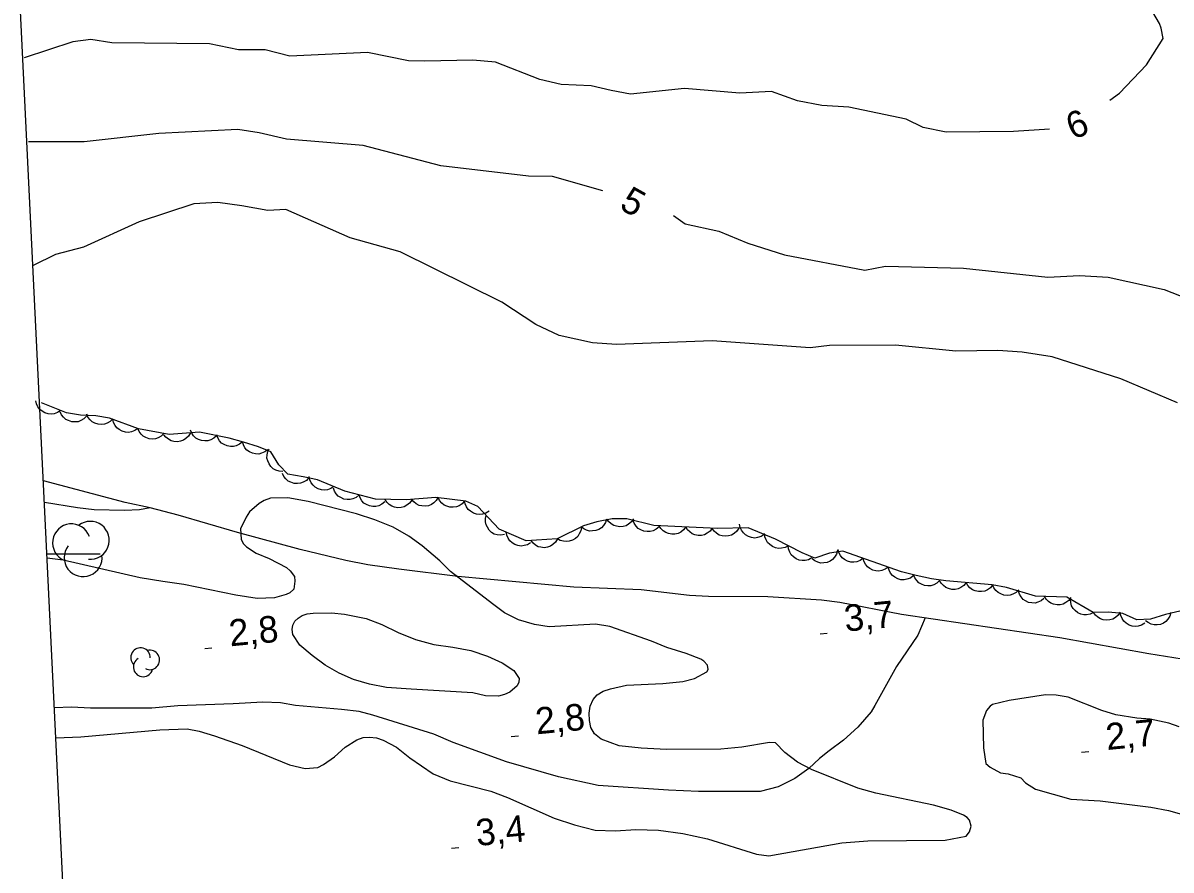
# Model space of a CAD drawing. Extents: x 336540 to 340074, y 5572036 to 5573747.
# Drawn here: x 336616 to 336745.5, y 5572364.3 to 5572459.9 of the extents above; entities that cross this region are included whole.
import ezdxf

# ---------------------------------------------------------------- set-up
doc = ezdxf.new("R2010")
doc.units = 0
for name, color, linetype in [('Niveau 1', 7, 'Continuous'), ('Niveau 2', 7, 'Continuous'), ('Niveau 22', 7, 'Continuous'), ('Niveau 3', 7, 'Continuous'), ('Niveau 44', 7, 'Continuous'), ('Niveau 60', 7, 'Continuous'), ('Niveau 61', 7, 'Continuous')]:
    doc.layers.add(name, color=color, linetype=linetype)

msp = doc.modelspace()

# ---------------------------------------------------------------- linework, layer by layer
at = {"layer": 'Niveau 1'}
for points in [[(336681.44, 5572440.96), (336675.75, 5572442.56), (336673.04, 5572442.6), (336663.17, 5572443.78), (336654.41, 5572446.05), (336645.76, 5572446.79), (336642.67, 5572447.49), (336640.29, 5572447.87), (336631.35, 5572447.41), (336622.95, 5572446.49), (336616.66, 5572446.48)], [(336689.41, 5572438.18), (336690.74, 5572437.24), (336694.51, 5572436.41), (336697.79, 5572435.05), (336701.93, 5572433.74), (336710.98, 5572432), (336713.32, 5572432.45), (336722.13, 5572432.24), (336731.65, 5572431.2), (336735.21, 5572431.39), (336738.42, 5572431.21), (336744.75, 5572429.83), (336750.81, 5572427.43)]]:
    msp.add_lwpolyline(points, dxfattribs=at)
at = {"layer": 'Niveau 2'}
for points in [[(336738.64, 5572451.17), (336739.72, 5572451.96), (336742.77, 5572455.17), (336744.66, 5572458.15), (336744.42, 5572459.32), (336744.22, 5572459.82), (336741.06, 5572465.25)], [(336731.81, 5572447.89), (336727.77, 5572447.63), (336720.16, 5572447.56), (336717.58, 5572448.11), (336715.67, 5572449.03), (336709.18, 5572450.39), (336706.14, 5572450.57), (336703.4, 5572451.12), (336700.45, 5572452.15), (336696.91, 5572451.97), (336690.64, 5572452.5), (336684.57, 5572451.84), (336682.37, 5572452.26), (336680.13, 5572452.8), (336676.74, 5572452.96), (336674.35, 5572453.53), (336669.33, 5572455.48), (336666.79, 5572455.7), (336661.38, 5572455.57), (336659.52, 5572455.63), (336654.9, 5572456.57), (336646.12, 5572456.13), (336643.37, 5572456.85), (336640.33, 5572456.86), (336637.08, 5572457.53), (336626.07, 5572457.65), (336623.68, 5572458.04), (336621.67, 5572457.77), (336616.17, 5572455.96)], [(336746.25, 5572417.02), (336739.86, 5572419.75), (336732.11, 5572422.23), (336728.72, 5572422.74), (336726, 5572422.94), (336721.25, 5572422.86), (336714.46, 5572423.53), (336707.02, 5572423.49), (336704.83, 5572423.22), (336693.79, 5572424.01), (336682.98, 5572423.6), (336680.26, 5572423.8), (336676.51, 5572424.64), (336673.9, 5572425.86), (336670.04, 5572428.38), (336658.58, 5572434.05), (336652.94, 5572435.63), (336645.67, 5572438.83), (336643.64, 5572438.72), (336640.73, 5572439.26), (336638.02, 5572439.62), (336635.31, 5572439.48), (336629.16, 5572437.45), (336622.87, 5572434.6), (336619.71, 5572433.75), (336617.19, 5572432.51)], [(336619.76, 5572379.24), (336622.56, 5572379.34), (336631.47, 5572380.14), (336634.56, 5572380.25), (336635.9, 5572379.98), (336637.65, 5572379.46), (336640.77, 5572378.35), (336646.1, 5572376.16), (336647.85, 5572375.75), (336649.3, 5572375.89), (336649.93, 5572376.2), (336651.17, 5572377.08), (336652.38, 5572378.17), (336653.7, 5572379.01), (336654.4, 5572379.25), (336655.14, 5572379.3), (336655.9, 5572379.22), (336656.65, 5572378.97), (336658.16, 5572378.16), (336659.66, 5572376.97), (336662.29, 5572375.16), (336664.23, 5572374.37), (336668.79, 5572373.21), (336670.68, 5572372.48), (336675.95, 5572370.16), (336678.24, 5572369.39), (336680.59, 5572368.79), (336682.86, 5572368.71), (336685.18, 5572368.87), (336687.71, 5572368.8), (336690.46, 5572368.44), (336693.23, 5572367.83), (336698.77, 5572366.11), (336700.16, 5572365.9), (336708.38, 5572367.37), (336711.34, 5572367.59), (336720.04, 5572367.69), (336722.41, 5572368.13), (336722.81, 5572368.6), (336722.98, 5572369.25), (336722.81, 5572369.92), (336722.54, 5572370.22), (336722.11, 5572370.5), (336720.72, 5572371.05), (336718.73, 5572371.61), (336712.22, 5572372.97), (336710.2, 5572373.56), (336704.98, 5572375.63), (336703.4, 5572376.46), (336701.96, 5572377.55), (336700.9, 5572378.66), (336700.25, 5572378.71), (336697.12, 5572378.15), (336694.76, 5572377.93), (336688.63, 5572377.92), (336685.75, 5572378.04), (336683.3, 5572378.32), (336681.26, 5572379.09), (336680.51, 5572379.69), (336680.1, 5572380.4), (336679.92, 5572381.18), (336679.9, 5572381.99), (336680.03, 5572382.79), (336680.35, 5572383.53), (336680.82, 5572384.08), (336681.49, 5572384.49), (336682.31, 5572384.77), (336684.11, 5572385.18), (336688.2, 5572385.35), (336690.45, 5572385.57), (336691.78, 5572385.91), (336693.16, 5572386.67), (336693.34, 5572386.94), (336693.25, 5572387.44), (336692.84, 5572387.89), (336692.49, 5572388.11), (336690.83, 5572388.73), (336688.65, 5572389.4), (336686.93, 5572390.14), (336682.22, 5572391.79), (336680.61, 5572392.06), (336675.39, 5572391.74), (336673.74, 5572392.02), (336671.94, 5572392.53), (336670.34, 5572393.34), (336669, 5572394.34), (336664.26, 5572397.99), (336663.04, 5572399.18), (336661.08, 5572400.9), (336659.57, 5572401.98), (336657.8, 5572402.99), (336655.72, 5572403.82), (336653.67, 5572404.51), (336648.19, 5572405.89), (336645.91, 5572406.31), (336643.94, 5572406.27), (336643.24, 5572406.01), (336642.66, 5572405.66), (336641.59, 5572404.72), (336641.2, 5572404.12), (336640.57, 5572402.79)], [(336640.57, 5572402.79), (336640.64, 5572401.65), (336640.87, 5572401.16), (336641.26, 5572400.76), (336642.33, 5572400.05), (336643.79, 5572399.45), (336645.76, 5572398.46), (336646.19, 5572398.07), (336646.66, 5572397.42), (336646.7, 5572396.89), (336646.59, 5572396), (336646.14, 5572395.58), (336645.72, 5572395.38), (336644.4, 5572395.01), (336642.47, 5572394.96), (336640.04, 5572395.31), (336634.18, 5572396.54), (336631.81, 5572396.85), (336629.27, 5572397.29), (336620.56, 5572399.28), (336618.77, 5572399.51)], [(336659.83, 5572384.73), (336657.04, 5572384.9), (336655.14, 5572385.26), (336653.33, 5572385.79), (336651.69, 5572386.53), (336650.14, 5572387.44), (336648.66, 5572388.51), (336647.26, 5572389.68), (336646.46, 5572390.89), (336646.4, 5572391.44), (336646.46, 5572391.95), (336646.7, 5572392.39), (336647.07, 5572392.73), (336647.54, 5572393.01), (336648.11, 5572393.21), (336648.76, 5572393.29), (336650.85, 5572393.33), (336652.32, 5572393.17), (336654.76, 5572392.69), (336656.53, 5572392.03), (336658.34, 5572391.12), (336660.3, 5572390.32), (336662.38, 5572389.77), (336664.51, 5572389.47), (336666.55, 5572389.06), (336668.44, 5572388.45), (336670.09, 5572387.69), (336671.41, 5572386.83), (336672, 5572385.93), (336671.96, 5572385.49), (336671.76, 5572385.1), (336670.96, 5572384.38), (336670.36, 5572384.1), (336669.67, 5572383.94), (336668.19, 5572383.97), (336666.77, 5572384.31), (336659.83, 5572384.73)], [(336746.46, 5572380.48), (336745.27, 5572380.89), (336743.19, 5572381.34), (336741.66, 5572381.45), (336739.32, 5572381.81), (336737.73, 5572382.3), (336733.91, 5572383.82), (336732.59, 5572384.05), (336731.38, 5572384.06), (336727.29, 5572383.42), (336725.39, 5572382.98), (336725.13, 5572382.81), (336724.72, 5572382.29), (336724.3, 5572381.21), (336724.38, 5572378.1), (336724.65, 5572376.33), (336725.12, 5572375.91), (336726.28, 5572375.29), (336727.16, 5572375.15), (336728.58, 5572374.71), (336729.13, 5572374.16), (336730.24, 5572373.42), (336734.22, 5572372.31)], [(336734.22, 5572372.31), (336737.53, 5572372.11), (336743.26, 5572371.39), (336745.26, 5572371.01), (336749.51, 5572369.81)]]:
    msp.add_lwpolyline(points, dxfattribs=at)
at = {"layer": 'Niveau 22'}
for points in [[(336746.78, 5572388.11), (336743.04, 5572388.69), (336733, 5572390.49), (336715.14, 5572393.15), (336708.18, 5572394.48), (336706.11, 5572394.76), (336700.06, 5572395.12), (336693.35, 5572395.17), (336691.23, 5572395.28), (336685.77, 5572395.92), (336678.18, 5572396.21), (336665.09, 5572397.41), (336658.42, 5572398.24), (336654.93, 5572398.74), (336652.44, 5572399.22), (336647.3, 5572400.46), (336640.25, 5572402.38), (336633.54, 5572404.36), (336630.38, 5572405.18), (336627.58, 5572405.79), (336618.34, 5572408.23)], [(336630.38, 5572405.18), (336629.18, 5572404.95), (336627.47, 5572404.89), (336624.06, 5572404.94), (336622.18, 5572405.17), (336618.46, 5572405.79)], [(336717.79, 5572392.75), (336716.98, 5572390.81), (336714.58, 5572387.29), (336712.13, 5572382.86), (336711.69, 5572382.17), (336710.2, 5572380.42), (336708.6, 5572378.95), (336706.98, 5572377.76), (336705.87, 5572376.88), (336704.68, 5572375.78), (336703.1, 5572374.62), (336701.21, 5572373.69), (336699.19, 5572373.16), (336692.24, 5572373.16), (336688.85, 5572373.31), (336680.93, 5572373.84), (336676.44, 5572374.81), (336670.58, 5572376.53), (336664.55, 5572378.7), (336662.38, 5572379.62), (336655.49, 5572381.77), (336653.96, 5572382.19), (336651.98, 5572382.43), (336646.77, 5572382.87), (336645.07, 5572383.17), (336643.09, 5572383.24), (336639.76, 5572383.04), (336633.49, 5572382.84), (336630.56, 5572382.57), (336623.66, 5572382.57), (336621.51, 5572382.69), (336619.58, 5572382.62)]]:
    msp.add_lwpolyline(points, dxfattribs=at)
at = {"layer": 'Niveau 3'}
for p, q in [((336705.94, 5572390.96), (336706.74, 5572391.04)), ((336636.54, 5572389.3), (336637.34, 5572389.38)), ((336671.11, 5572379.37), (336671.91, 5572379.45)), ((336735.44, 5572377.6), (336736.24, 5572377.68)), ((336664.39, 5572366.77), (336665.19, 5572366.85))]:
    msp.add_line(p, q, dxfattribs=at)
at = {"layer": 'Niveau 44'}
for points in [[(336620.28, 5572416.16), (336619.94, 5572415.93), (336619.55, 5572415.8), (336619.23, 5572415.74), (336618.88, 5572415.78), (336618.52, 5572415.89), (336618.19, 5572416.08), (336617.93, 5572416.28), (336617.73, 5572416.57), (336617.57, 5572416.9), (336617.49, 5572417.25)], [(336748.3, 5572393.92), (336744.89, 5572393.15), (336743.22, 5572392.62), (336741.68, 5572392.54), (336740.09, 5572393.24), (336738.42, 5572393.39), (336736.75, 5572393.38), (336733.76, 5572395.08), (336730.25, 5572395.22), (336726.98, 5572396.18), (336725.36, 5572396.49), (336720.13, 5572396.93), (336718.5, 5572397.17), (336716.79, 5572397.55), (336715.11, 5572397.97), (336708.51, 5572400.29), (336707.01, 5572400.06), (336705.36, 5572399.51), (336703.94, 5572400.08), (336700.92, 5572401.63), (336697.84, 5572402.92), (336694.33, 5572402.85), (336687.19, 5572403.19), (336684.16, 5572403.94), (336682.48, 5572403.92), (336680.76, 5572403.58), (336679.26, 5572403.13), (336676.28, 5572401.66), (336672.79, 5572401.46), (336669.74, 5572402.78), (336667.34, 5572405.34), (336665.97, 5572405.93), (336662.61, 5572406.36), (336659.27, 5572406.07), (336655.8, 5572406.14), (336652.33, 5572407.07), (336649.26, 5572408.32), (336647.63, 5572408.69), (336645.91, 5572408.96), (336644.91, 5572410.02), (336644, 5572411.5), (336642.59, 5572412.07), (336640.91, 5572412.59), (336639.29, 5572413.03), (336635.96, 5572413.72), (336632.54, 5572413.47), (336629.08, 5572414.1), (336625.81, 5572415.28), (336624.27, 5572415.55), (336622.52, 5572415.64), (336620.96, 5572415.9), (336618.11, 5572417.01)], [(336623.2, 5572415.53), (336622.92, 5572415.22), (336622.56, 5572415.02), (336622.26, 5572414.9), (336621.91, 5572414.87), (336621.54, 5572414.9), (336621.17, 5572415.02), (336620.88, 5572415.16), (336620.62, 5572415.4), (336620.39, 5572415.69), (336620.24, 5572416.02)], [(336626.18, 5572415.21), (336625.89, 5572414.91), (336625.54, 5572414.72), (336625.23, 5572414.6), (336624.88, 5572414.57), (336624.51, 5572414.6), (336624.15, 5572414.73), (336623.85, 5572414.87), (336623.6, 5572415.11), (336623.37, 5572415.4), (336623.23, 5572415.73)], [(336628.99, 5572414.13), (336628.65, 5572413.89), (336628.26, 5572413.75), (336627.94, 5572413.69), (336627.59, 5572413.72), (336627.23, 5572413.81), (336626.9, 5572414), (336626.63, 5572414.19), (336626.42, 5572414.47), (336626.25, 5572414.8), (336626.16, 5572415.15)], [(336631.93, 5572413.58), (336631.64, 5572413.28), (336631.28, 5572413.09), (336630.98, 5572412.97), (336630.63, 5572412.94), (336630.26, 5572412.97), (336629.9, 5572413.11), (336629.6, 5572413.25), (336629.35, 5572413.49), (336629.13, 5572413.79), (336628.98, 5572414.12)], [(336634.92, 5572413.64), (336634.71, 5572413.28), (336634.41, 5572413), (336634.14, 5572412.81), (336633.81, 5572412.7), (336633.45, 5572412.64), (336633.07, 5572412.67), (336632.75, 5572412.74), (336632.44, 5572412.91), (336632.15, 5572413.14), (336631.93, 5572413.43)], [(336637.87, 5572413.32), (336637.57, 5572413.03), (336637.21, 5572412.85), (336636.9, 5572412.73), (336636.55, 5572412.72), (336636.18, 5572412.76), (336635.83, 5572412.9), (336635.54, 5572413.05), (336635.29, 5572413.3), (336635.07, 5572413.6), (336634.94, 5572413.93)], [(336640.79, 5572412.62), (336640.47, 5572412.35), (336640.1, 5572412.19), (336639.78, 5572412.09), (336639.43, 5572412.1), (336639.07, 5572412.16), (336638.72, 5572412.32), (336638.44, 5572412.49), (336638.21, 5572412.75), (336638.01, 5572413.07), (336637.89, 5572413.41)], [(336643.66, 5572411.74), (336643.33, 5572411.48), (336642.95, 5572411.33), (336642.63, 5572411.25), (336642.28, 5572411.26), (336641.92, 5572411.34), (336641.58, 5572411.51), (336641.3, 5572411.69), (336641.08, 5572411.96), (336640.9, 5572412.28), (336640.79, 5572412.63)], [(336645.36, 5572409.29), (336644.94, 5572409.31), (336644.56, 5572409.44), (336644.26, 5572409.59), (336644.01, 5572409.83), (336643.79, 5572410.13), (336643.65, 5572410.49), (336643.56, 5572410.8), (336643.57, 5572411.15), (336643.64, 5572411.52), (336643.79, 5572411.84)], [(336648.28, 5572408.59), (336648, 5572408.28), (336647.65, 5572408.08), (336647.34, 5572407.95), (336646.99, 5572407.92), (336646.62, 5572407.94), (336646.26, 5572408.06), (336645.96, 5572408.2), (336645.7, 5572408.44), (336645.47, 5572408.73), (336645.32, 5572409.05)], [(336651.1, 5572407.57), (336650.75, 5572407.34), (336650.37, 5572407.22), (336650.04, 5572407.17), (336649.69, 5572407.21), (336649.34, 5572407.32), (336649.01, 5572407.52), (336648.75, 5572407.72), (336648.55, 5572408.01), (336648.4, 5572408.35), (336648.32, 5572408.7)], [(336653.95, 5572406.64), (336653.63, 5572406.36), (336653.26, 5572406.2), (336652.94, 5572406.1), (336652.59, 5572406.11), (336652.23, 5572406.17), (336651.88, 5572406.33), (336651.6, 5572406.5), (336651.36, 5572406.76), (336651.17, 5572407.07), (336651.05, 5572407.41)], [(336656.84, 5572405.86), (336656.53, 5572405.59), (336656.16, 5572405.42), (336655.84, 5572405.33), (336655.49, 5572405.33), (336655.13, 5572405.39), (336654.78, 5572405.55), (336654.5, 5572405.72), (336654.26, 5572405.98), (336654.06, 5572406.3), (336653.95, 5572406.64)], [(336659.88, 5572406.06), (336659.64, 5572405.72), (336659.32, 5572405.47), (336659.03, 5572405.3), (336658.69, 5572405.22), (336658.32, 5572405.19), (336657.95, 5572405.26), (336657.63, 5572405.36), (336657.34, 5572405.56), (336657.08, 5572405.82), (336656.88, 5572406.12)], [(336662.87, 5572406.38), (336662.66, 5572406.02), (336662.37, 5572405.74), (336662.11, 5572405.54), (336661.77, 5572405.42), (336661.41, 5572405.36), (336661.03, 5572405.39), (336660.71, 5572405.45), (336660.4, 5572405.62), (336660.11, 5572405.84), (336659.88, 5572406.12)], [(336665.84, 5572405.95), (336665.57, 5572405.63), (336665.22, 5572405.42), (336664.92, 5572405.28), (336664.57, 5572405.24), (336664.2, 5572405.25), (336663.83, 5572405.36), (336663.53, 5572405.49), (336663.27, 5572405.72), (336663.03, 5572406.01), (336662.87, 5572406.33)], [(336668.61, 5572404.79), (336668.25, 5572404.57), (336667.86, 5572404.46), (336667.54, 5572404.41), (336667.19, 5572404.46), (336666.84, 5572404.58), (336666.52, 5572404.79), (336666.26, 5572404.99), (336666.07, 5572405.29), (336665.92, 5572405.63), (336665.85, 5572405.98)], [(336670.34, 5572402.15), (336669.92, 5572402.08), (336669.52, 5572402.13), (336669.2, 5572402.22), (336668.9, 5572402.41), (336668.63, 5572402.66), (336668.42, 5572402.98), (336668.27, 5572403.26), (336668.21, 5572403.61), (336668.2, 5572403.98), (336668.28, 5572404.33)], [(336684.89, 5572403.95), (336684.66, 5572403.6), (336684.35, 5572403.34), (336684.07, 5572403.16), (336683.73, 5572403.07), (336683.36, 5572403.03), (336682.98, 5572403.09), (336682.67, 5572403.18), (336682.37, 5572403.37), (336682.09, 5572403.62), (336681.89, 5572403.91)], [(336679.02, 5572403.01), (336678.96, 5572402.6), (336678.79, 5572402.23), (336678.61, 5572401.95), (336678.35, 5572401.72), (336678.03, 5572401.52), (336677.66, 5572401.42), (336677.34, 5572401.36), (336676.99, 5572401.4), (336676.64, 5572401.5), (336676.33, 5572401.68)], [(336681.87, 5572403.91), (336681.75, 5572403.52), (336681.52, 5572403.18), (336681.3, 5572402.93), (336681, 5572402.75), (336680.66, 5572402.61), (336680.27, 5572402.57), (336679.95, 5572402.56), (336679.61, 5572402.66), (336679.28, 5572402.82), (336679, 5572403.05)], [(336687.78, 5572403.04), (336687.47, 5572402.76), (336687.1, 5572402.59), (336686.79, 5572402.49), (336686.43, 5572402.49), (336686.07, 5572402.54), (336685.72, 5572402.7), (336685.43, 5572402.86), (336685.2, 5572403.12), (336684.99, 5572403.43), (336684.87, 5572403.76)], [(336690.79, 5572403.02), (336690.54, 5572402.68), (336690.22, 5572402.44), (336689.93, 5572402.28), (336689.58, 5572402.21), (336689.21, 5572402.2), (336688.84, 5572402.28), (336688.53, 5572402.38), (336688.24, 5572402.59), (336687.98, 5572402.85), (336687.8, 5572403.16)], [(336693.79, 5572402.88), (336693.54, 5572402.54), (336693.21, 5572402.3), (336692.92, 5572402.14), (336692.58, 5572402.07), (336692.21, 5572402.05), (336691.83, 5572402.14), (336691.52, 5572402.24), (336691.24, 5572402.45), (336690.98, 5572402.71), (336690.79, 5572403.02)], [(336696.79, 5572402.9), (336696.56, 5572402.55), (336696.25, 5572402.29), (336695.97, 5572402.11), (336695.63, 5572402.01), (336695.27, 5572401.97), (336694.89, 5572402.03), (336694.57, 5572402.11), (336694.27, 5572402.3), (336694, 5572402.55), (336693.79, 5572402.84)], [(336699.64, 5572402.17), (336699.29, 5572401.94), (336698.9, 5572401.82), (336698.57, 5572401.77), (336698.22, 5572401.82), (336697.87, 5572401.94), (336697.55, 5572402.14), (336697.29, 5572402.34), (336697.09, 5572402.64), (336696.94, 5572402.97), (336696.87, 5572403.33)], [(336673.29, 5572401.24), (336672.94, 5572401.02), (336672.55, 5572400.91), (336672.22, 5572400.86), (336671.87, 5572400.92), (336671.52, 5572401.03), (336671.2, 5572401.24), (336670.95, 5572401.45), (336670.76, 5572401.74), (336670.61, 5572402.08), (336670.54, 5572402.43)], [(336676.33, 5572401.66), (336676.12, 5572401.3), (336675.82, 5572401.03), (336675.54, 5572400.84), (336675.21, 5572400.73), (336674.84, 5572400.68), (336674.46, 5572400.72), (336674.15, 5572400.79), (336673.84, 5572400.97), (336673.55, 5572401.21), (336673.34, 5572401.49)], [(336702.35, 5572400.9), (336701.99, 5572400.69), (336701.59, 5572400.61), (336701.26, 5572400.59), (336700.91, 5572400.66), (336700.57, 5572400.8), (336700.27, 5572401.03), (336700.03, 5572401.25), (336699.85, 5572401.56), (336699.73, 5572401.91), (336699.68, 5572402.27)], [(336705.02, 5572399.53), (336704.65, 5572399.32), (336704.26, 5572399.24), (336703.93, 5572399.22), (336703.58, 5572399.29), (336703.24, 5572399.43), (336702.93, 5572399.66), (336702.7, 5572399.88), (336702.52, 5572400.19), (336702.4, 5572400.54), (336702.35, 5572400.9)], [(336707.91, 5572400.36), (336707.79, 5572399.96), (336707.58, 5572399.61), (336707.36, 5572399.36), (336707.07, 5572399.17), (336706.73, 5572399.02), (336706.35, 5572398.96), (336706.02, 5572398.95), (336705.68, 5572399.04), (336705.35, 5572399.19), (336705.06, 5572399.41)], [(336710.8, 5572399.48), (336710.46, 5572399.24), (336710.08, 5572399.1), (336709.76, 5572399.03), (336709.41, 5572399.06), (336709.05, 5572399.15), (336708.71, 5572399.34), (336708.45, 5572399.52), (336708.23, 5572399.8), (336708.06, 5572400.13), (336707.97, 5572400.48)], [(336713.63, 5572398.49), (336713.3, 5572398.24), (336712.91, 5572398.1), (336712.59, 5572398.04), (336712.24, 5572398.06), (336711.88, 5572398.16), (336711.55, 5572398.34), (336711.28, 5572398.53), (336711.07, 5572398.81), (336710.89, 5572399.14), (336710.8, 5572399.48)], [(336716.46, 5572397.5), (336716.13, 5572397.25), (336715.74, 5572397.11), (336715.42, 5572397.04), (336715.07, 5572397.07), (336714.71, 5572397.16), (336714.38, 5572397.35), (336714.11, 5572397.53), (336713.9, 5572397.81), (336713.72, 5572398.14), (336713.63, 5572398.49)], [(336719.43, 5572396.96), (336719.12, 5572396.68), (336718.76, 5572396.5), (336718.45, 5572396.39), (336718.09, 5572396.38), (336717.73, 5572396.42), (336717.37, 5572396.57), (336717.09, 5572396.72), (336716.84, 5572396.98), (336716.63, 5572397.28), (336716.5, 5572397.62)], [(336722.42, 5572396.74), (336722.16, 5572396.41), (336721.82, 5572396.18), (336721.53, 5572396.04), (336721.18, 5572395.97), (336720.81, 5572395.97), (336720.44, 5572396.07), (336720.14, 5572396.18), (336719.86, 5572396.4), (336719.61, 5572396.67), (336719.43, 5572396.99)], [(336725.41, 5572396.49), (336725.15, 5572396.16), (336724.81, 5572395.93), (336724.52, 5572395.78), (336724.17, 5572395.72), (336723.8, 5572395.72), (336723.43, 5572395.82), (336723.13, 5572395.93), (336722.85, 5572396.15), (336722.6, 5572396.42), (336722.42, 5572396.74)], [(336728.36, 5572395.92), (336728.06, 5572395.62), (336727.7, 5572395.43), (336727.4, 5572395.31), (336727.04, 5572395.29), (336726.68, 5572395.33), (336726.32, 5572395.46), (336726.03, 5572395.61), (336725.77, 5572395.85), (336725.55, 5572396.15), (336725.41, 5572396.48)], [(336731.2, 5572394.94), (336730.88, 5572394.67), (336730.51, 5572394.52), (336730.19, 5572394.43), (336729.84, 5572394.44), (336729.47, 5572394.51), (336729.13, 5572394.68), (336728.85, 5572394.85), (336728.63, 5572395.12), (336728.44, 5572395.44), (336728.33, 5572395.78)], [(336734.24, 5572395.06), (336733.99, 5572394.72), (336733.67, 5572394.48), (336733.38, 5572394.32), (336733.04, 5572394.24), (336732.67, 5572394.23), (336732.29, 5572394.31), (336731.98, 5572394.41), (336731.7, 5572394.61), (336731.43, 5572394.87), (336731.24, 5572395.18)], [(336736.79, 5572393.36), (336736.41, 5572393.17), (336736.01, 5572393.11), (336735.68, 5572393.1), (336735.34, 5572393.19), (336735.01, 5572393.34), (336734.71, 5572393.58), (336734.48, 5572393.82), (336734.32, 5572394.13), (336734.21, 5572394.48), (336734.18, 5572394.84)], [(336739.79, 5572393.4), (336739.56, 5572393.05), (336739.25, 5572392.79), (336738.97, 5572392.62), (336738.63, 5572392.53), (336738.26, 5572392.49), (336737.88, 5572392.55), (336737.57, 5572392.64), (336737.27, 5572392.83), (336737, 5572393.08), (336736.79, 5572393.38)], [(336742.56, 5572392.15), (336742.2, 5572391.93), (336741.81, 5572391.82), (336741.48, 5572391.78), (336741.14, 5572391.84), (336740.79, 5572391.95), (336740.47, 5572392.17), (336740.21, 5572392.37), (336740.02, 5572392.67), (336739.88, 5572393.01), (336739.81, 5572393.36)], [(336745.52, 5572393.35), (336745.41, 5572392.95), (336745.18, 5572392.61), (336744.96, 5572392.36), (336744.67, 5572392.17), (336744.33, 5572392.03), (336743.95, 5572391.98), (336743.62, 5572391.97), (336743.28, 5572392.06), (336742.95, 5572392.22), (336742.66, 5572392.44)]]:
    msp.add_lwpolyline(points, dxfattribs=at)
for centre, radius, start, end in [((336621.51, 5572401.23), 2.14, 19.8636, 247.3207), ((336623.63, 5572401.51), 2.14, 264.5313, 127.2156), ((336622.82, 5572399.55), 2.14, 141.7098, 7.3984), ((336629.29, 5572388.28), 1.1, 357.9691, 225.4262), ((336630.35, 5572388.01), 1.1, 242.6368, 105.3212), ((336629.59, 5572387.22), 1.1, 119.8153, 345.5039)]:
    msp.add_arc(centre, radius, start, end, dxfattribs=at)
at = {"layer": 'Niveau 60'}
msp.add_lwpolyline([(339458.94, 5573698.73), (339531.5, 5572199.65), (336635.22, 5572059.46), (336562.66, 5573558.54), (339458.94, 5573698.73)], dxfattribs=at)
at = {"layer": 'Niveau 61'}
msp.add_lwpolyline([(336618.74, 5572400), (336624.74, 5572400)], dxfattribs=at)

# ---------------------------------------------------------------- texts
at = {"layer": 'Niveau 1'}
msp.add_text('5', height=3, rotation=330.8458, dxfattribs=at).set_placement((336683.18, 5572438.98))
at = {"layer": 'Niveau 2'}
msp.add_text('6', height=3, rotation=21.9696, dxfattribs=at).set_placement((336734.45, 5572446.68))
at = {"layer": 'Niveau 3'}
for s, p in [('3,7    ', (336708.81, 5572391.2)), ('2,8    ', (336639.41, 5572389.54)), ('2,8    ', (336673.98, 5572379.61)), ('2,7    ', (336738.31, 5572377.84)), ('3,4    ', (336667.26, 5572367.01))]:
    msp.add_text(s, height=3, rotation=5.5424, dxfattribs=at).set_placement(p)

doc.saveas('drawing.dxf')
